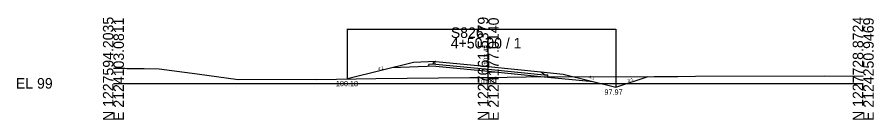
# Model space of a CAD drawing. Extents: x 2118382 to 2118616, y 1213030 to 1222057.
# Drawn here: x 2118381.9 to 2118610.4, y 1215030.1 to 1215057.4 of the extents above; entities that cross this region are included whole.
import ezdxf

# ---------------------------------------------------------------- set-up
doc = ezdxf.new("R2010")
doc.units = 0
for name, color, linetype in [('XS_CELL', 7, 'Continuous'), ('XS_M_DITCH', 7, 'Continuous'), ('XS_P_FINISHED_GRADE', 7, 'Continuous'), ('XS_P_FINISHED_GRADE_ELEV_TX', 7, 'Continuous'), ('XS_P_SUBGRADE_GRANULAR', 7, 'Continuous'), ('XS_P_SUBGRADE_PAVEMENT', 7, 'Continuous'), ('XS_P_TX_DCH', 7, 'Continuous'), ('XS_P_TX_FS_BS', 7, 'Continuous'), ('XS_X_GROUND', 7, 'Continuous'), ('XS_X_GROUND_TX', 7, 'Continuous')]:
    doc.layers.add(name, color=color, linetype=linetype)

msp = doc.modelspace()

# ---------------------------------------------------------------- linework, layer by layer
at = {"layer": 'XS_CELL'}
for p, q in [((2118507.6, 1215039.8), (2118507.6, 1215051.88)), ((2118407.6, 1215039.8), (2118507.6, 1215039.8)), ((2118507.6, 1215039.8), (2118607.6, 1215039.8))]:
    msp.add_line(p, q, dxfattribs=at)
at = {"layer": 'XS_M_DITCH'}
for p, q in [((2118470.01, 1215054.24), (2118541.6, 1215054.24)), ((2118470.03, 1215040.99), (2118470.03, 1215054.25)), ((2118541.6, 1215054.24), (2118541.6, 1215038.78))]:
    msp.add_line(p, q, dxfattribs=at)
at = {"layer": 'XS_P_FINISHED_GRADE'}
for p, q in [((2118487.6, 1215045.38), (2118470.03, 1215040.99)), ((2118493.6, 1215045.62), (2118487.6, 1215045.38)), ((2118493.6, 1215045.62), (2118507.6, 1215044.24)), ((2118507.6, 1215044.24), (2118521.6, 1215042.87)), ((2118521.6, 1215042.87), (2118527.6, 1215042.28)), ((2118527.6, 1215042.28), (2118541.6, 1215038.78)), ((2118541.6, 1215038.78), (2118550.2, 1215041.64))]:
    msp.add_line(p, q, dxfattribs=at)
at = {"layer": 'XS_P_SUBGRADE_GRANULAR'}
for p, q in [((2118493.6, 1215044.41), (2118481.82, 1215043.93)), ((2118492.76, 1215044.88), (2118491.76, 1215044.84)), ((2118491.76, 1215044.33), (2118491.76, 1215044.84)), ((2118493.6, 1215044.41), (2118507.6, 1215043.03)), ((2118507.6, 1215043.03), (2118521.6, 1215041.65)), ((2118521.6, 1215041.65), (2118535.61, 1215040.28)), ((2118522.48, 1215042.07), (2118523.45, 1215042.03)), ((2118523.45, 1215041.47), (2118523.45, 1215042.03))]:
    msp.add_line(p, q, dxfattribs=at)
at = {"layer": 'XS_P_SUBGRADE_PAVEMENT'}
for p, q in [((2118492.91, 1215045.13), (2118492.76, 1215044.88)), ((2118493.6, 1215044.91), (2118492.76, 1215044.88)), ((2118493.6, 1215045.62), (2118492.91, 1215045.13)), ((2118493.6, 1215044.91), (2118507.6, 1215043.53)), ((2118507.6, 1215043.53), (2118522.48, 1215042.07)), ((2118521.6, 1215042.87), (2118522.3, 1215042.38)), ((2118522.3, 1215042.38), (2118522.48, 1215042.07))]:
    msp.add_line(p, q, dxfattribs=at)
at = {"layer": 'XS_X_GROUND'}
for p, q in [((2118407.6, 1215043.84), (2118410.64, 1215043.8)), ((2118410.64, 1215043.8), (2118411.21, 1215043.79)), ((2118411.21, 1215043.79), (2118414.94, 1215043.73)), ((2118414.94, 1215043.73), (2118415.79, 1215043.72)), ((2118415.79, 1215043.72), (2118419.83, 1215043.65)), ((2118419.83, 1215043.65), (2118429.96, 1215042.31)), ((2118429.96, 1215042.31), (2118440.91, 1215040.83)), ((2118507.6, 1215041.39), (2118517.68, 1215041.57)), ((2118517.68, 1215041.57), (2118551.82, 1215041.65)), ((2118551.82, 1215041.66), (2118558.15, 1215041.64)), ((2118558.15, 1215041.64), (2118562.83, 1215041.68)), ((2118562.83, 1215041.68), (2118597.23, 1215041.8)), ((2118597.23, 1215041.8), (2118607.6, 1215041.74)), ((2118440.91, 1215040.83), (2118461.87, 1215040.87)), ((2118461.87, 1215040.86), (2118477.62, 1215041.11)), ((2118477.62, 1215041.11), (2118502.67, 1215041.31)), ((2118502.67, 1215041.31), (2118507.6, 1215041.39))]:
    msp.add_line(p, q, dxfattribs=at)

# ---------------------------------------------------------------- texts
at = {"layer": 'XS_CELL'}
for s, p in [('N 1227594.2035', (2118407.6, 1215029.8)), ('E 2124103.0811', (2118410.4, 1215029.8)), ('N 1227661.5379', (2118507.6, 1215029.8)), ('E 2124177.0140', (2118510.4, 1215029.8)), ('N 1227728.8724', (2118607.6, 1215029.8)), ('E 2124250.9469', (2118610.4, 1215029.8))]:
    msp.add_text(s, height=2.8, rotation=90, dxfattribs=at).set_placement(p)
for s, p in [('S826', (2118497.6, 1215051.88)), ('4+50.00 / 1', (2118497.6, 1215049.08)), ('EL 99', (2118381.6, 1215038.4))]:
    msp.add_text(s, height=2.8, dxfattribs=at).set_placement(p)
at = {"layer": 'XS_P_FINISHED_GRADE_ELEV_TX'}
msp.add_text(' 103.44', height=1.25, rotation=90, dxfattribs=at).set_placement((2118507.6, 1215044.23))
at = {"layer": 'XS_P_TX_DCH'}
for s, p in [('100.18', (2118466.93, 1215039.04)), ('97.97', (2118538.58, 1215036.78))]:
    msp.add_text(s, height=1.4, dxfattribs=at).set_placement(p)
at = {"layer": 'XS_P_TX_FS_BS'}
for s, rotation, p in [('4:1', 14.0362, (2118478.28, 1215043.23)), ('4:1', 345.9638, (2118534.33, 1215041.14)), ('3:1', 18.4349, (2118544.9, 1215040.09))]:
    msp.add_text(s, height=0.8, rotation=rotation, dxfattribs=at).set_placement(p)
at = {"layer": 'XS_X_GROUND_TX'}
msp.add_text('100.59', height=1, dxfattribs=at).set_placement((2118504.91, 1215039.82))

doc.saveas('drawing.dxf')
